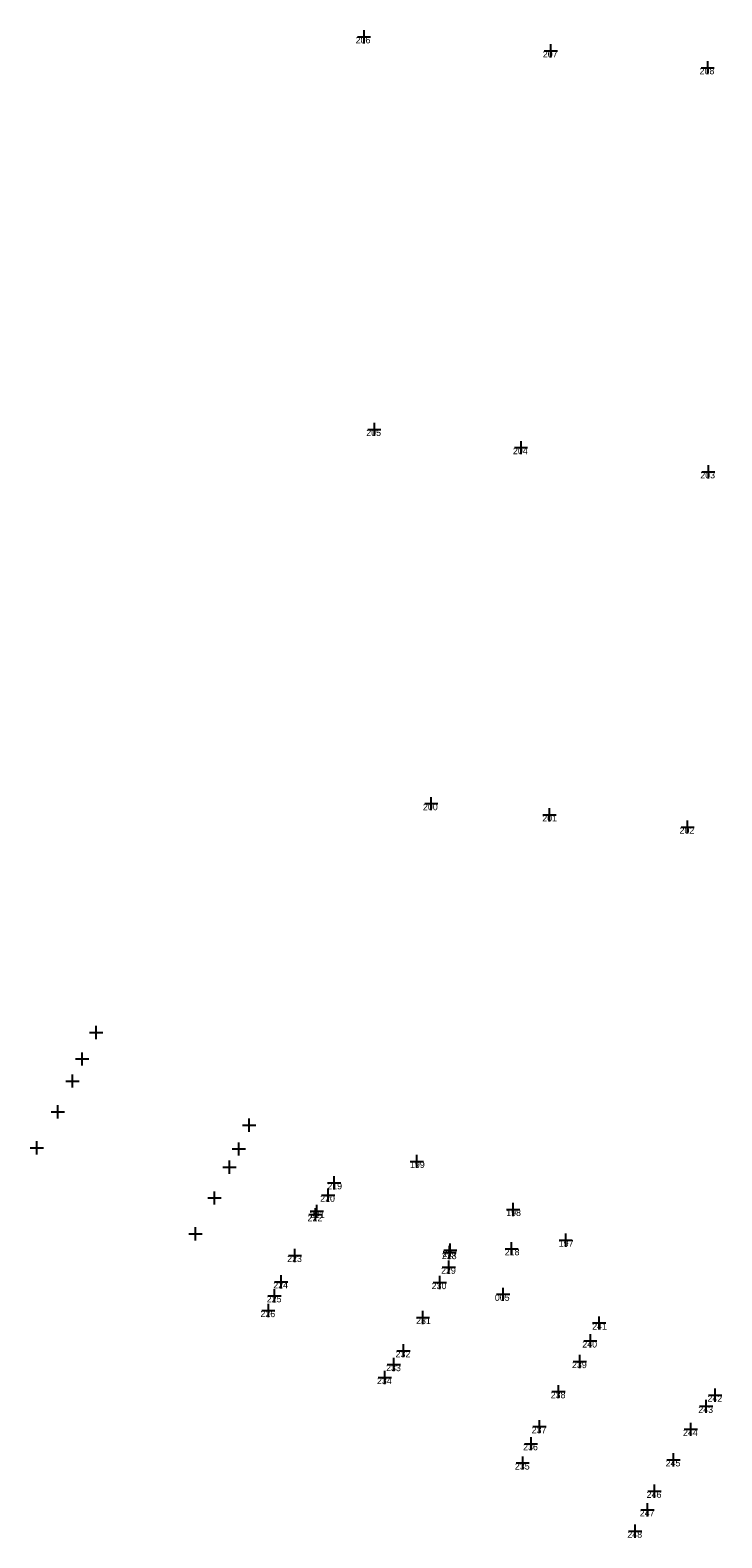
# Model space of a CAD drawing. Extents: x -706655 to -706193, y -1036183 to -1035040.
# Drawn here: x -706294.5 to -706242.2, y -1036182.5 to -1036068.4 of the extents above; entities that cross this region are included whole.
import ezdxf

# ---------------------------------------------------------------- set-up
doc = ezdxf.new("R2010")
doc.units = 0
doc.layers.add('čísla bodu', color=7, linetype='Continuous')

msp = doc.modelspace()

# ---------------------------------------------------------------- linework, layer by layer
at = {"layer": 'čísla bodu'}
for p, q in [((-706269.23, -1036069.38), (-706269.23, -1036068.38)), ((-706269.73, -1036068.88), (-706268.73, -1036068.88)), ((-706269.23, -1036068.88), (-706269.23, -1036068.88)), ((-706255.09, -1036070.45), (-706255.09, -1036069.45)), ((-706255.59, -1036069.95), (-706254.59, -1036069.95)), ((-706255.09, -1036069.95), (-706255.09, -1036069.95)), ((-706243.22, -1036071.72), (-706243.22, -1036070.72)), ((-706243.72, -1036071.22), (-706242.72, -1036071.22)), ((-706243.22, -1036071.22), (-706243.22, -1036071.22)), ((-706268.45, -1036099.1), (-706268.45, -1036098.1)), ((-706268.95, -1036098.6), (-706267.95, -1036098.6)), ((-706268.45, -1036098.6), (-706268.45, -1036098.6)), ((-706257.85, -1036099.98), (-706256.85, -1036099.98)), ((-706257.35, -1036100.48), (-706257.35, -1036099.48)), ((-706257.35, -1036099.98), (-706257.35, -1036099.98)), ((-706243.17, -1036102.31), (-706243.17, -1036101.31)), ((-706243.67, -1036101.81), (-706242.67, -1036101.81)), ((-706243.17, -1036101.81), (-706243.17, -1036101.81)), ((-706264.14, -1036127.43), (-706264.14, -1036126.43)), ((-706264.64, -1036126.93), (-706263.64, -1036126.93)), ((-706264.14, -1036126.93), (-706264.14, -1036126.93)), ((-706255.7, -1036127.78), (-706254.7, -1036127.78)), ((-706255.2, -1036128.28), (-706255.2, -1036127.28)), ((-706255.2, -1036127.78), (-706255.2, -1036127.78)), ((-706245.24, -1036128.7), (-706244.24, -1036128.7)), ((-706244.74, -1036129.2), (-706244.74, -1036128.2)), ((-706244.74, -1036128.7), (-706244.74, -1036128.7)), ((-706289.51, -1036144.75), (-706289.51, -1036143.75)), ((-706289.51, -1036144.75), (-706289.51, -1036143.75)), ((-706290.01, -1036144.25), (-706289.01, -1036144.25)), ((-706290.01, -1036144.25), (-706289.01, -1036144.25)), ((-706289.51, -1036144.25), (-706289.51, -1036144.25)), ((-706289.51, -1036144.25), (-706289.51, -1036144.25)), ((-706290.56, -1036146.76), (-706290.56, -1036145.76)), ((-706290.56, -1036146.76), (-706290.56, -1036145.76)), ((-706291.06, -1036146.26), (-706290.06, -1036146.26)), ((-706291.06, -1036146.26), (-706290.06, -1036146.26)), ((-706290.56, -1036146.26), (-706290.56, -1036146.26)), ((-706290.56, -1036146.26), (-706290.56, -1036146.26)), ((-706291.8, -1036147.93), (-706290.8, -1036147.93)), ((-706291.8, -1036147.93), (-706290.8, -1036147.93)), ((-706291.3, -1036148.43), (-706291.3, -1036147.43)), ((-706291.3, -1036148.43), (-706291.3, -1036147.43)), ((-706291.3, -1036147.93), (-706291.3, -1036147.93)), ((-706291.3, -1036147.93), (-706291.3, -1036147.93)), ((-706292.9, -1036150.26), (-706291.9, -1036150.26)), ((-706292.9, -1036150.26), (-706291.9, -1036150.26)), ((-706292.4, -1036150.76), (-706292.4, -1036149.76)), ((-706292.4, -1036150.76), (-706292.4, -1036149.76)), ((-706292.4, -1036150.26), (-706292.4, -1036150.26)), ((-706292.4, -1036150.26), (-706292.4, -1036150.26)), ((-706277.93, -1036151.77), (-706277.93, -1036150.77)), ((-706277.93, -1036151.77), (-706277.93, -1036150.77)), ((-706278.43, -1036151.27), (-706277.43, -1036151.27)), ((-706278.43, -1036151.27), (-706277.43, -1036151.27)), ((-706277.93, -1036151.27), (-706277.93, -1036151.27)), ((-706277.93, -1036151.27), (-706277.93, -1036151.27)), ((-706294.5, -1036152.99), (-706293.5, -1036152.99)), ((-706294.5, -1036152.99), (-706293.5, -1036152.99)), ((-706294, -1036153.49), (-706294, -1036152.49)), ((-706294, -1036153.49), (-706294, -1036152.49)), ((-706294, -1036152.99), (-706294, -1036152.99)), ((-706294, -1036152.99), (-706294, -1036152.99)), ((-706278.7, -1036153.57), (-706278.7, -1036152.57)), ((-706278.7, -1036153.57), (-706278.7, -1036152.57)), ((-706279.42, -1036154.94), (-706279.42, -1036153.94)), ((-706279.42, -1036154.94), (-706279.42, -1036153.94)), ((-706279.2, -1036153.07), (-706278.2, -1036153.07)), ((-706279.2, -1036153.07), (-706278.2, -1036153.07)), ((-706278.7, -1036153.07), (-706278.7, -1036153.07)), ((-706278.7, -1036153.07), (-706278.7, -1036153.07)), ((-706265.73, -1036154.01), (-706264.73, -1036154.01)), ((-706265.23, -1036154.51), (-706265.23, -1036153.51)), ((-706265.23, -1036154.01), (-706265.23, -1036154.01)), ((-706279.92, -1036154.44), (-706278.92, -1036154.44)), ((-706279.92, -1036154.44), (-706278.92, -1036154.44)), ((-706279.42, -1036154.44), (-706279.42, -1036154.44)), ((-706279.42, -1036154.44), (-706279.42, -1036154.44)), ((-706271.49, -1036156.13), (-706271.49, -1036155.13)), ((-706280.55, -1036157.28), (-706280.55, -1036156.28)), ((-706280.55, -1036157.28), (-706280.55, -1036156.28)), ((-706271.99, -1036155.63), (-706270.99, -1036155.63)), ((-706271.94, -1036157.07), (-706271.94, -1036156.07)), ((-706271.49, -1036155.63), (-706271.49, -1036155.63)), ((-706281.05, -1036156.78), (-706280.05, -1036156.78)), ((-706281.05, -1036156.78), (-706280.05, -1036156.78)), ((-706280.55, -1036156.78), (-706280.55, -1036156.78)), ((-706280.55, -1036156.78), (-706280.55, -1036156.78)), ((-706272.91, -1036158.54), (-706272.91, -1036157.54)), ((-706272.81, -1036158.29), (-706272.81, -1036157.29)), ((-706272.44, -1036156.57), (-706271.44, -1036156.57)), ((-706271.94, -1036156.57), (-706271.94, -1036156.57)), ((-706257.95, -1036158.15), (-706257.95, -1036157.15)), ((-706273.41, -1036158.04), (-706272.41, -1036158.04)), ((-706273.31, -1036157.79), (-706272.31, -1036157.79)), ((-706272.91, -1036158.04), (-706272.91, -1036158.04)), ((-706272.81, -1036157.79), (-706272.81, -1036157.79)), ((-706258.45, -1036157.65), (-706257.45, -1036157.65)), ((-706257.95, -1036157.65), (-706257.95, -1036157.65)), ((-706282.48, -1036159.49), (-706281.48, -1036159.49)), ((-706282.48, -1036159.49), (-706281.48, -1036159.49)), ((-706281.98, -1036159.99), (-706281.98, -1036158.99)), ((-706281.98, -1036159.99), (-706281.98, -1036158.99)), ((-706281.98, -1036159.49), (-706281.98, -1036159.49)), ((-706281.98, -1036159.49), (-706281.98, -1036159.49)), ((-706253.97, -1036160.47), (-706253.97, -1036159.47)), ((-706274.46, -1036161.63), (-706274.46, -1036160.63)), ((-706263.25, -1036160.91), (-706262.25, -1036160.91)), ((-706263.2, -1036160.72), (-706262.2, -1036160.72)), ((-706262.75, -1036161.41), (-706262.75, -1036160.41)), ((-706262.75, -1036160.91), (-706262.75, -1036160.91)), ((-706262.7, -1036161.22), (-706262.7, -1036160.22)), ((-706262.7, -1036160.72), (-706262.7, -1036160.72)), ((-706258.56, -1036160.62), (-706257.56, -1036160.62)), ((-706258.06, -1036161.12), (-706258.06, -1036160.12)), ((-706258.06, -1036160.62), (-706258.06, -1036160.62)), ((-706254.47, -1036159.97), (-706253.47, -1036159.97)), ((-706253.97, -1036159.97), (-706253.97, -1036159.97)), ((-706274.96, -1036161.13), (-706273.96, -1036161.13)), ((-706274.46, -1036161.13), (-706274.46, -1036161.13)), ((-706263.31, -1036162.02), (-706262.31, -1036162.02)), ((-706262.81, -1036162.52), (-706262.81, -1036161.52)), ((-706262.81, -1036162.02), (-706262.81, -1036162.02)), ((-706276.01, -1036163.13), (-706275.01, -1036163.13)), ((-706275.51, -1036163.63), (-706275.51, -1036162.63)), ((-706275.51, -1036163.13), (-706275.51, -1036163.13)), ((-706264, -1036163.18), (-706263, -1036163.18)), ((-706263.5, -1036163.68), (-706263.5, -1036162.68)), ((-706263.5, -1036163.18), (-706263.5, -1036163.18)), ((-706276.5, -1036164.18), (-706275.5, -1036164.18)), ((-706276, -1036164.68), (-706276, -1036163.68)), ((-706276, -1036164.18), (-706276, -1036164.18)), ((-706259.2, -1036164.07), (-706258.2, -1036164.07)), ((-706258.7, -1036164.57), (-706258.7, -1036163.57)), ((-706258.7, -1036164.07), (-706258.7, -1036164.07)), ((-706276.97, -1036165.3), (-706275.97, -1036165.3)), ((-706276.47, -1036165.8), (-706276.47, -1036164.8)), ((-706276.47, -1036165.3), (-706276.47, -1036165.3)), ((-706264.77, -1036166.32), (-706264.77, -1036165.32)), ((-706265.27, -1036165.82), (-706264.27, -1036165.82)), ((-706264.77, -1036165.82), (-706264.77, -1036165.82)), ((-706251.94, -1036166.24), (-706250.94, -1036166.24)), ((-706251.44, -1036166.74), (-706251.44, -1036165.74)), ((-706251.44, -1036166.24), (-706251.44, -1036166.24)), ((-706266.25, -1036168.84), (-706266.25, -1036167.84)), ((-706252.6, -1036167.6), (-706251.6, -1036167.6)), ((-706252.1, -1036168.1), (-706252.1, -1036167.1)), ((-706252.1, -1036167.6), (-706252.1, -1036167.6)), ((-706266.97, -1036169.89), (-706266.97, -1036168.89)), ((-706266.75, -1036168.34), (-706265.75, -1036168.34)), ((-706266.25, -1036168.34), (-706266.25, -1036168.34)), ((-706252.9, -1036169.66), (-706252.9, -1036168.66)), ((-706267.66, -1036170.87), (-706267.66, -1036169.87)), ((-706267.47, -1036169.39), (-706266.47, -1036169.39)), ((-706266.97, -1036169.39), (-706266.97, -1036169.39)), ((-706253.4, -1036169.16), (-706252.4, -1036169.16)), ((-706252.9, -1036169.16), (-706252.9, -1036169.16)), ((-706268.16, -1036170.37), (-706267.16, -1036170.37)), ((-706267.66, -1036170.37), (-706267.66, -1036170.37)), ((-706254.51, -1036171.94), (-706254.51, -1036170.94)), ((-706242.65, -1036172.21), (-706242.65, -1036171.21)), ((-706255.01, -1036171.44), (-706254.01, -1036171.44)), ((-706254.51, -1036171.44), (-706254.51, -1036171.44)), ((-706243.34, -1036173.05), (-706243.34, -1036172.05)), ((-706243.15, -1036171.71), (-706242.15, -1036171.71)), ((-706242.65, -1036171.71), (-706242.65, -1036171.71)), ((-706255.95, -1036174.59), (-706255.95, -1036173.59)), ((-706243.84, -1036172.55), (-706242.84, -1036172.55)), ((-706243.34, -1036172.55), (-706243.34, -1036172.55)), ((-706256.45, -1036174.09), (-706255.45, -1036174.09)), ((-706255.95, -1036174.09), (-706255.95, -1036174.09)), ((-706245, -1036174.29), (-706244, -1036174.29)), ((-706244.5, -1036174.79), (-706244.5, -1036173.79)), ((-706244.5, -1036174.29), (-706244.5, -1036174.29)), ((-706257.09, -1036175.38), (-706256.09, -1036175.38)), ((-706256.59, -1036175.88), (-706256.59, -1036174.88)), ((-706256.59, -1036175.38), (-706256.59, -1036175.38)), ((-706257.72, -1036176.84), (-706256.72, -1036176.84)), ((-706257.22, -1036177.34), (-706257.22, -1036176.34)), ((-706257.22, -1036176.84), (-706257.22, -1036176.84)), ((-706246.31, -1036176.6), (-706245.31, -1036176.6)), ((-706245.81, -1036177.1), (-706245.81, -1036176.1)), ((-706245.81, -1036176.6), (-706245.81, -1036176.6)), ((-706247.74, -1036178.98), (-706246.74, -1036178.98)), ((-706247.24, -1036179.48), (-706247.24, -1036178.48)), ((-706247.24, -1036178.98), (-706247.24, -1036178.98)), ((-706248.27, -1036180.38), (-706247.27, -1036180.38)), ((-706247.77, -1036180.88), (-706247.77, -1036179.88)), ((-706247.77, -1036180.38), (-706247.77, -1036180.38)), ((-706248.71, -1036182.5), (-706248.71, -1036181.5)), ((-706249.21, -1036182), (-706248.21, -1036182)), ((-706248.71, -1036182), (-706248.71, -1036182))]:
    msp.add_line(p, q, dxfattribs=at)

# ---------------------------------------------------------------- texts
for s, p in [('206', (-706269.86, -1036069.38)), ('207', (-706255.7, -1036070.45)), ('208', (-706243.83, -1036071.72)), ('205', (-706269.06, -1036099.1)), ('204', (-706257.96, -1036100.48)), ('203', (-706243.78, -1036102.31)), ('200', (-706264.77, -1036127.43)), ('201', (-706255.74, -1036128.28)), ('202', (-706245.35, -1036129.2)), ('199', (-706265.75, -1036154.51)), ('219', (-706272.01, -1036156.13)), ('220', (-706272.55, -1036157.07)), ('222', (-706273.5, -1036158.54)), ('221', (-706273.33, -1036158.29)), ('198', (-706258.47, -1036158.15)), ('228', (-706263.34, -1036161.41)), ('227', (-706263.29, -1036161.22)), ('218', (-706258.58, -1036161.12)), ('197', (-706254.49, -1036160.47)), ('223', (-706275.05, -1036161.63)), ('229', (-706263.4, -1036162.52)), ('224', (-706276.1, -1036163.63)), ('230', (-706264.11, -1036163.68)), ('225', (-706276.59, -1036164.68)), ('005', (-706259.33, -1036164.57)), ('226', (-706277.07, -1036165.8)), ('231', (-706265.29, -1036166.32)), ('241', (-706251.96, -1036166.74)), ('240', (-706252.71, -1036168.1)), ('232', (-706266.84, -1036168.84)), ('233', (-706267.56, -1036169.89)), ('239', (-706253.49, -1036169.66)), ('234', (-706268.25, -1036170.87)), ('238', (-706255.1, -1036171.94)), ('242', (-706243.24, -1036172.21)), ('243', (-706243.93, -1036173.05)), ('237', (-706256.54, -1036174.59)), ('244', (-706245.09, -1036174.79)), ('236', (-706257.19, -1036175.88)), ('235', (-706257.81, -1036177.34)), ('245', (-706246.4, -1036177.1)), ('246', (-706247.84, -1036179.48)), ('247', (-706248.36, -1036180.88)), ('248', (-706249.3, -1036182.5))]:
    msp.add_text(s, height=0.5, dxfattribs=at).set_placement(p)

doc.saveas('drawing.dxf')
